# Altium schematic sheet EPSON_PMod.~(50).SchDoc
size A4
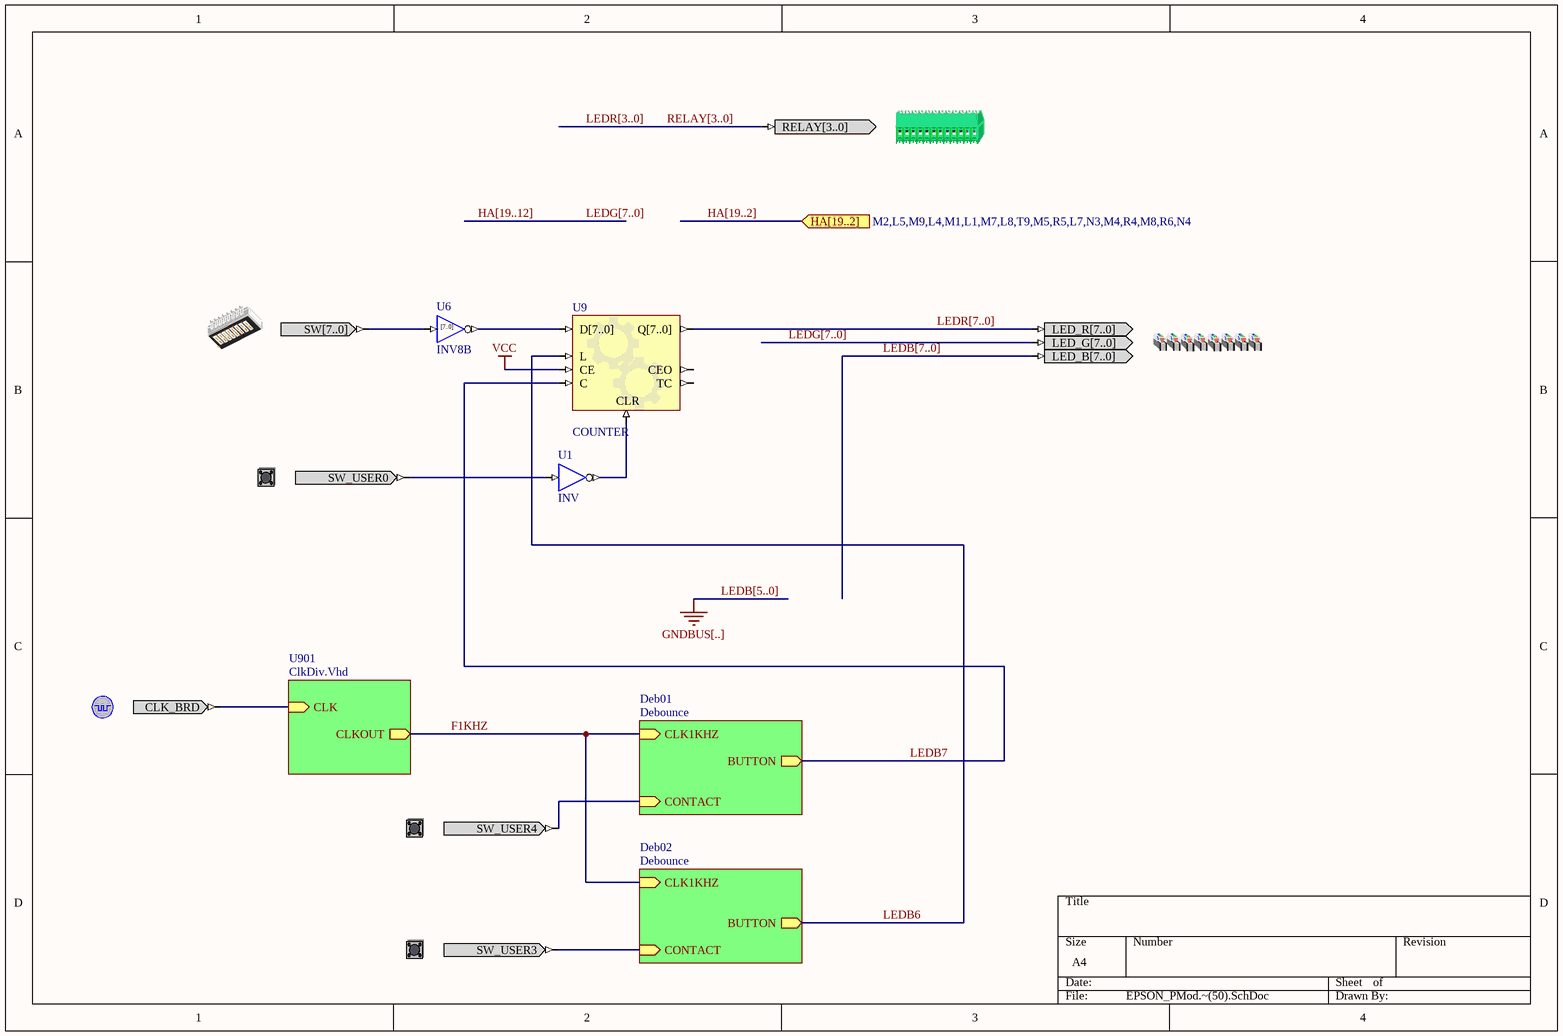
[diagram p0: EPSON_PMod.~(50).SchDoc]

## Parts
(Parts that share a designator on the sheet are numbered #1, #2 ... from top to bottom, then left to right.)
?#1  RELAYCNTR  (value not drawn)
?#2  DIPSWITCH  (value not drawn)
?#3  LEDS_RGB  (value not drawn)
?#4  USER_BUTTON0  (value not drawn)
?#5  CLOCK_BOARD  (value not drawn)
?#6  USER_BUTTON4  (value not drawn)
?#7  USER_BUTTON3  (value not drawn)
U1  INV
U6  INV8B
U9  COUNTER

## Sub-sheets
Deb01 = Debounce: CONTACT (in), BUTTON (out), CLK1KHZ (in)
Deb02 = Debounce: CONTACT (in), BUTTON (out), CLK1KHZ (in)
U901 = ClkDiv.Vhd: CLK (in), CLKOUT (out)

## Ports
HA[19..2] (in, see M2,L5,M9,L4,M1,L1,M7,L8,T9,M5,R5,L7,N3,M4,R4,M8,R6,N4)

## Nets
VCC: U9.CE
F1KHZ: sheet U901/CLKOUT, sheet Deb01/CLK1KHZ, sheet Deb02/CLK1KHZ
LEDB6: U9.L ; sheet Deb02/BUTTON
LEDB7: U9.C ; sheet Deb01/BUTTON
Net?#4_SW_USER0: ?#4.SW_USER0 U1.I
Net?#5_CLK_BRD: ?#5.CLK_BRD ; sheet U901/CLK
Net?#6_SW_USER4: ?#6.SW_USER4 ; sheet Deb01/CONTACT
Net?#7_SW_USER3: ?#7.SW_USER3 ; sheet Deb02/CONTACT
NetU1_O: U1.O U9.CLR

Not connected (* = marked no-connect by the designer): ?#1 RELAY[3..0]; ?#2 SW[7..0]; ?#3 LED_B[7..0] LED_G[7..0] LED_R[7..0]; U6 I[7..0] O[7..0]; U9 CEO D[7..0] Q[7..0] TC

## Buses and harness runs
bus HA[19..2] = port HA[19..2]
bus HA[19..12] = LEDG[7..0]
bus LEDB[5..0]
bus LEDB[7..0]
bus LEDG[7..0]
bus LEDR[3..0] = RELAY[3..0]
bus LEDR[7..0]

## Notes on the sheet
- Labels drawn without touching a wire or pin: GNDBUS[..]

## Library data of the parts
?#1 = RELAYCNTR: RELAY; PortComponent: True
?#2 = DIPSWITCH: 8-Way Dip-Switch; PortComponent: True
?#3 = LEDS_RGB: LEDS RGB; PortComponent: True
?#4 = USER_BUTTON0: Generic User Button; PortComponent: True
?#5 = CLOCK_BOARD: Global System Clock Supply; PortComponent: True
?#6 = USER_BUTTON4: Generic User Button; PortComponent: True
?#7 = USER_BUTTON3: Generic User Button; PortComponent: True
U1 = INV: Inverter; FunctionalClass: Logic Primitive; ArchiveName: GENERIC; VHDLIB_SIM: GENERIC_LIB
U6 = INV8B: 8-Bit Inverter, Bus Version; XilinxEquivalent: INV8; FunctionalClass: Logic Primitive; SubClass: INV; PortSize: 8; ArchiveName: GENERIC; VHDLIB_SIM: GENERIC_LIB
U9 = COUNTER: Configurable Counter; ConfiguratorName: GENERIC_COUNTER; ConfigurationParameters: {}Version[1.0]{}Type[Binary]{}SyncReset[False]{}NegativeClockEdge[False]{}FixedDirection[True]{}IsIncrement[True]{}SignalWidth[8]{}MaxValue[255]{}BusOutput[True]{}Loadable[True]{}BusInput[True]{}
